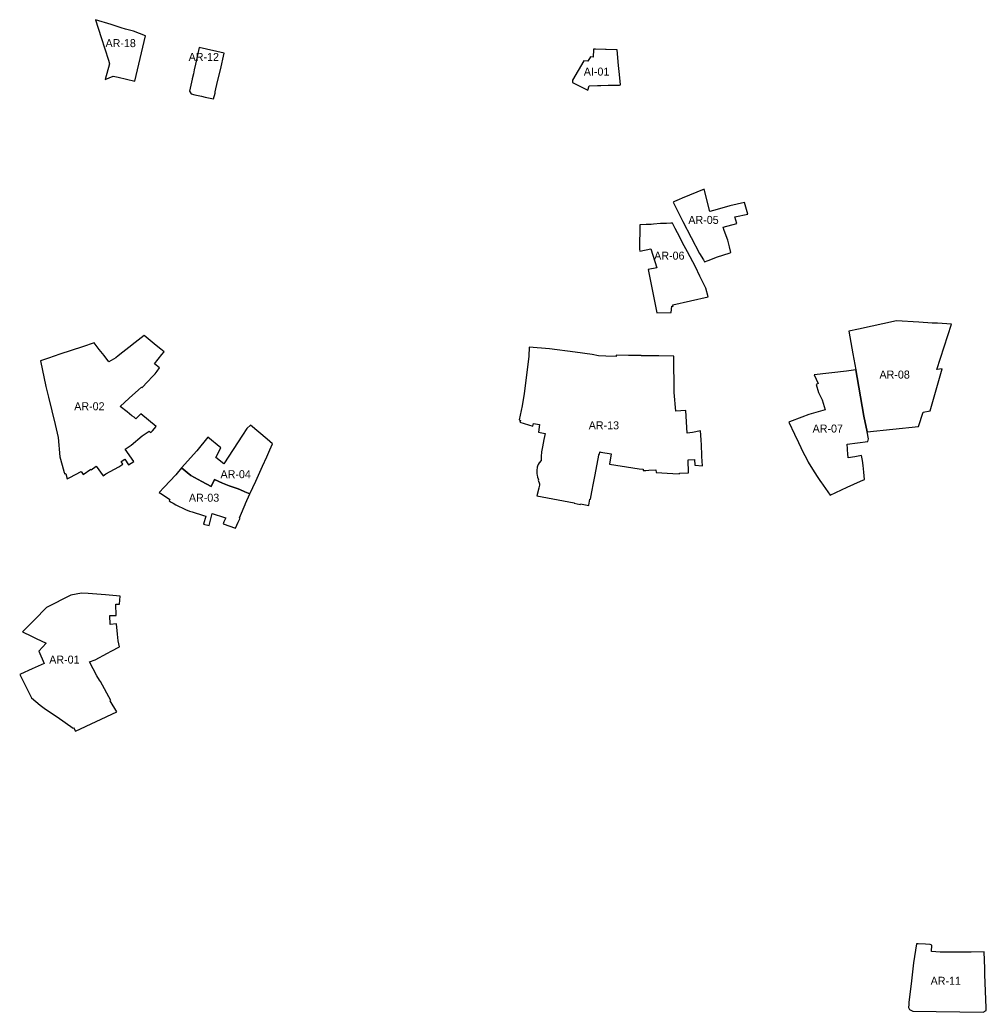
# Model space of a CAD drawing. Extents: x 428342 to 437063, y 4455780 to 4463043.
# Drawn here: x 432214 to 432818, y 4459120 to 4459741 of the extents above; entities that cross this region are included whole.
import ezdxf

# ---------------------------------------------------------------- set-up
doc = ezdxf.new("R2010")
doc.units = 0
doc.layers.add('AMB_SUNC-Residenciales', color=7, linetype='Continuous')
doc.layers.add('AMB_SUNC-Txt', color=7, linetype='Continuous')

msp = doc.modelspace()

# ---------------------------------------------------------------- linework, layer by layer
at = {"layer": 'AMB_SUNC-Residenciales'}
for points in [[(432270.35, 4459713.21), (432267.73, 4459703.42), (432272.76, 4459705.39), (432275.92, 4459704.68), (432286.32, 4459702.35), (432292.84, 4459730.56), (432285.51, 4459733.43), (432280.41, 4459734.7), (432277.62, 4459735.58), (432276.44, 4459735.97), (432271.44, 4459737.62), (432261.68, 4459740.6), (432265.15, 4459729.51), (432269.69, 4459715.37), (432270.35, 4459713.21)], [(432342.14, 4459719.79), (432326.52, 4459723.22), (432324.25, 4459712.99), (432323.44, 4459709.32), (432322.91, 4459706.96), (432322.19, 4459703.71), (432322.14, 4459703.52), (432320.34, 4459696.08), (432321.48, 4459694.34), (432323.81, 4459693.8), (432327.86, 4459692.88), (432330.27, 4459692.36), (432335.52, 4459691.23), (432336.37, 4459694.86), (432336.55, 4459695.66), (432338.01, 4459702.16), (432339.77, 4459709.35), (432342.14, 4459719.79)], [(432569.51, 4459714.84), (432566.86, 4459714.98), (432559.8, 4459702.83), (432559.91, 4459701.51), (432563.12, 4459699.68), (432564.42, 4459699.06), (432569.51, 4459696.65), (432570.25, 4459699.43), (432575.45, 4459699.48), (432577.63, 4459699.56), (432582.17, 4459699.68), (432588.31, 4459699.75), (432589.27, 4459699.85), (432589.85, 4459699.91), (432589.18, 4459706.35), (432588.59, 4459712.15), (432587.67, 4459721.79), (432580.79, 4459721.98), (432580.54, 4459721.99), (432574.23, 4459722.25), (432572.97, 4459722.3), (432572.96, 4459722.1), (432572.8, 4459717.31), (432571.17, 4459717.43), (432569.51, 4459714.84)], [(432628.44, 4459629.17), (432626.54, 4459628.31), (432623.62, 4459627), (432622.77, 4459626.65), (432628.84, 4459614.53), (432639.28, 4459594.68), (432641.69, 4459590.58), (432642.37, 4459589.38), (432644.64, 4459590.25), (432650.44, 4459592.46), (432657.72, 4459594.79), (432658.76, 4459595.13), (432657.9, 4459598.73), (432656.91, 4459602.88), (432654.67, 4459608.98), (432654, 4459611.1), (432662.45, 4459613.3), (432661.37, 4459617.5), (432669.38, 4459619.27), (432668.99, 4459620.66), (432667.31, 4459626.56), (432658.07, 4459624.28), (432650.23, 4459622.09), (432645.68, 4459620.87), (432642.03, 4459634.71), (432637.63, 4459632.92), (432628.44, 4459629.17)], [(432624.07, 4459610.27), (432622.38, 4459613.54), (432621.28, 4459613.5), (432618.64, 4459613.4), (432614.81, 4459613.25), (432610.49, 4459612.87), (432609.02, 4459612.78), (432605.86, 4459612.62), (432601.92, 4459612.42), (432601.64, 4459597.33), (432601.91, 4459596.05), (432608.83, 4459597.54), (432612.62, 4459585.66), (432607.06, 4459584.51), (432611.24, 4459563.86), (432612.51, 4459557.59), (432621.42, 4459557.64), (432621.9, 4459561.57), (432622.74, 4459561.71), (432622.51, 4459562.54), (432644.57, 4459567.52), (432643.09, 4459572.95), (432639.46, 4459580.5), (432636.69, 4459586.35), (432631.67, 4459595.62), (432629.68, 4459599.45), (432625.53, 4459607.45), (432624.07, 4459610.27)], [(432741.87, 4459492.97), (432744.01, 4459483.08), (432776.05, 4459486.51), (432778.94, 4459495.45), (432783.39, 4459496.18), (432790.86, 4459522.43), (432787.59, 4459522.13), (432796.76, 4459550.45), (432788.03, 4459550.95), (432784.54, 4459551.15), (432776.27, 4459551.64), (432762.42, 4459552.54), (432738.59, 4459547.39), (432732.57, 4459546.08), (432735.12, 4459531.88), (432736.92, 4459521.86), (432737.79, 4459517.06), (432741.87, 4459492.97)], [(432299.49, 4459537.19), (432292.18, 4459543.43), (432290.26, 4459541.92), (432286.48, 4459538.97), (432282.59, 4459535.93), (432278.76, 4459532.95), (432275.87, 4459530.69), (432274.27, 4459529.45), (432270.04, 4459526.96), (432266.99, 4459530.78), (432263.94, 4459534.62), (432260.73, 4459538.67), (432253.53, 4459536.31), (432239.37, 4459531.66), (432232.3, 4459529.25), (432227.23, 4459527.51), (432230.7, 4459511.44), (432231.5, 4459508.15), (432232.33, 4459504.73), (432236.51, 4459487.66), (432238.4, 4459479.69), (432239.35, 4459467.46), (432240.84, 4459462.31), (432242.05, 4459457.83), (432242.28, 4459456.92), (432243, 4459457.11), (432243.03, 4459456.97), (432244.03, 4459453.75), (432245.61, 4459454.59), (432252.65, 4459458.36), (432253.96, 4459456.44), (432258.73, 4459459.72), (432259, 4459459.37), (432262.02, 4459461.63), (432266.42, 4459455.72), (432268.03, 4459456.92), (432276.31, 4459461.31), (432278.81, 4459462.89), (432277.74, 4459464.57), (432279.99, 4459466), (432282.25, 4459462.43), (432285.64, 4459464.59), (432280.24, 4459472.34), (432283.96, 4459474.9), (432290.82, 4459480.74), (432295.22, 4459483.62), (432296.32, 4459482.76), (432297.22, 4459483.8), (432299.59, 4459486.52), (432290.09, 4459494.48), (432286.88, 4459491.29), (432285.93, 4459492.21), (432284.4, 4459493.24), (432281.41, 4459495.61), (432277.13, 4459499.01), (432282.71, 4459504.14), (432288.57, 4459509.46), (432290.41, 4459511.03), (432290.78, 4459510.78), (432294.16, 4459514.42), (432297.29, 4459517.69), (432298.97, 4459519.45), (432300.14, 4459521.01), (432301.66, 4459523.05), (432298.47, 4459525.72), (432303.21, 4459531.45), (432304.6, 4459533.17), (432302.44, 4459534.76), (432299.49, 4459537.19)], [(432631.42, 4459482.24), (432630.58, 4459496.38), (432624.4, 4459496.06), (432623.39, 4459507.79), (432623.24, 4459530.41), (432613.77, 4459530.6), (432608.49, 4459530.6), (432602.84, 4459530.62), (432602.82, 4459530.83), (432594.91, 4459530.91), (432587.14, 4459531), (432587.11, 4459530.3), (432580.7, 4459530.48), (432576.1, 4459530.73), (432572.17, 4459531.42), (432561.58, 4459532.95), (432545.46, 4459534.97), (432532.83, 4459535.95), (432532.44, 4459530.5), (432531.46, 4459521.96), (432529.55, 4459507.12), (432528.37, 4459499.45), (432526.47, 4459490.54), (432527.24, 4459490.16), (432526.89, 4459489.22), (432534.96, 4459486.71), (432535.36, 4459488.28), (432539.1, 4459487.69), (432538.57, 4459483.03), (432542.74, 4459482.19), (432541.88, 4459478.37), (432540.97, 4459473.69), (432540.53, 4459470.69), (432540.32, 4459467.67), (432540.16, 4459465.29), (432538.99, 4459463.73), (432538.45, 4459462.76), (432538, 4459461.66), (432537.78, 4459460.97), (432537.67, 4459460.43), (432537.56, 4459459.64), (432537.46, 4459458.65), (432537.47, 4459457.48), (432537.53, 4459456.82), (432537.69, 4459456.01), (432538.04, 4459454.76), (432538.52, 4459453.4), (432538.46, 4459453.02), (432539.21, 4459450.61), (432539.12, 4459449.81), (432538.73, 4459448.17), (432538.7, 4459448.04), (432537.56, 4459443.15), (432560.93, 4459438.69), (432560.89, 4459438.54), (432564.68, 4459437.75), (432564.76, 4459438.12), (432570.06, 4459437.2), (432570.09, 4459437.35), (432570.71, 4459441.16), (432571.03, 4459441.1), (432571.89, 4459445.64), (432572.92, 4459451.03), (432573.94, 4459456.31), (432576.32, 4459468.59), (432576.38, 4459468.88), (432576.74, 4459469.16), (432576.95, 4459470.6), (432577.61, 4459470.48), (432584.01, 4459469.35), (432582.89, 4459462.89), (432597.48, 4459460.64), (432601.51, 4459460.09), (432604.04, 4459459.75), (432603.96, 4459458.98), (432604.78, 4459458.96), (432605.57, 4459458.96), (432607.54, 4459459.09), (432612.01, 4459459.39), (432612.22, 4459457.81), (432622.59, 4459457.13), (432626.76, 4459456.86), (432626.77, 4459457.39), (432632.23, 4459457.42), (432632.07, 4459465.64), (432636.12, 4459465.86), (432636.21, 4459462.24), (432641.01, 4459461.93), (432640.7, 4459467.81), (432640.39, 4459475.63), (432640.32, 4459477.4), (432640.29, 4459478.18), (432639.87, 4459483.67), (432634.81, 4459482.8), (432631.42, 4459482.24)], [(432744.92, 4459478.85), (432744.01, 4459483.08), (432741.87, 4459492.97), (432737.79, 4459517.06), (432736.92, 4459521.86), (432731, 4459521.15), (432710.97, 4459518.75), (432713.33, 4459513.28), (432712.19, 4459512.77), (432713.68, 4459507.7), (432715.85, 4459503.12), (432717.73, 4459496.99), (432707.48, 4459493.95), (432703.08, 4459492.36), (432695.38, 4459489.32), (432695.02, 4459489.18), (432698.63, 4459481.69), (432701.18, 4459476.41), (432702.63, 4459473.37), (432704.08, 4459470.33), (432706, 4459466.57), (432707.13, 4459464.16), (432709.87, 4459459.76), (432712.81, 4459455.19), (432714.93, 4459452.09), (432715.12, 4459451.81), (432720.8, 4459443.53), (432731.54, 4459448.54), (432739.87, 4459452.3), (432742.41, 4459453.35), (432741.93, 4459457.9), (432741.49, 4459462.1), (432741.1, 4459465.22), (432740.53, 4459468.34), (432736.35, 4459467.61), (432732.16, 4459466.87), (432731.95, 4459469.65), (432731.79, 4459471.68), (432731.73, 4459472.53), (432731.52, 4459475.42), (432744.45, 4459477.13), (432744.92, 4459478.85)], [(432328.05, 4459452.13), (432334.06, 4459449.01), (432336.09, 4459453.43), (432341.1, 4459451.1), (432345.21, 4459449.43), (432350.12, 4459447.71), (432351.79, 4459447.08), (432355.04, 4459445.68), (432358.2, 4459444.32), (432361.86, 4459452.38), (432366.05, 4459461.61), (432368.7, 4459467.45), (432370.72, 4459471.9), (432372.38, 4459475.55), (432368.97, 4459478.48), (432358.64, 4459487.33), (432356.35, 4459485.19), (432353.61, 4459481.04), (432341.83, 4459463.23), (432336.92, 4459467.05), (432340.09, 4459473.15), (432331.8, 4459479.72), (432324.92, 4459471.25), (432315.52, 4459460.6), (432321.34, 4459455.83), (432328.05, 4459452.13)], [(432301.54, 4459445.33), (432303.56, 4459443.97), (432308.19, 4459440.85), (432307.74, 4459440.01), (432308.97, 4459439.29), (432310.22, 4459438.57), (432311.88, 4459437.62), (432317.88, 4459434.54), (432320.47, 4459433.66), (432322.1, 4459433.18), (432329.13, 4459430.87), (432330.53, 4459430.53), (432329.22, 4459425.44), (432332.62, 4459424.56), (432334.6, 4459432.19), (432342.4, 4459429.61), (432343.06, 4459429.32), (432341.91, 4459426.9), (432341.48, 4459425.59), (432349.13, 4459423.04), (432350.81, 4459426.6), (432352.04, 4459429.23), (432351.61, 4459429.42), (432352.23, 4459430.87), (432355.12, 4459437.68), (432355.42, 4459438.39), (432358.2, 4459444.32), (432355.04, 4459445.68), (432351.79, 4459447.08), (432350.12, 4459447.71), (432345.21, 4459449.43), (432341.1, 4459451.1), (432336.09, 4459453.43), (432334.06, 4459449.01), (432328.05, 4459452.13), (432321.34, 4459455.83), (432315.52, 4459460.6), (432311.79, 4459456.19), (432304.57, 4459448.54), (432301.54, 4459445.33)], [(432247.93, 4459298.38), (432249.23, 4459296.17), (432274.95, 4459308.1), (432270.93, 4459315.13), (432271.25, 4459315.31), (432264.85, 4459327.1), (432264.24, 4459327.99), (432262.49, 4459330.57), (432257.9, 4459339.42), (432261.47, 4459340.72), (432269.08, 4459344.87), (432271.49, 4459346.13), (432276.65, 4459348.83), (432275.73, 4459352.51), (432275.39, 4459356.69), (432274.87, 4459363.12), (432270.84, 4459362.73), (432270.52, 4459368.41), (432274.49, 4459368.31), (432274.35, 4459375.38), (432276.64, 4459375.37), (432277.13, 4459380.53), (432267.93, 4459381.18), (432257.16, 4459382.06), (432252.89, 4459382.33), (432246.27, 4459381.06), (432231.05, 4459373.41), (432223.5, 4459365.76), (432215.95, 4459358.12), (432221.69, 4459355.39), (432224.6, 4459354.01), (432230.75, 4459351.08), (432226.24, 4459346.02), (432229.64, 4459338.36), (432222.1, 4459335.01), (432214.85, 4459331.8), (432214.37, 4459331.59), (432221.67, 4459316.87), (432224.33, 4459314.59), (432226.99, 4459312.31), (432230.5, 4459309.82), (432237.64, 4459305.12), (432247.62, 4459298.06), (432247.93, 4459298.38)], [(432803.7, 4459158), (432795.37, 4459158.04), (432789.66, 4459157.93), (432784.2, 4459158.42), (432784.47, 4459162.44), (432783.36, 4459162.83), (432780.42, 4459162.92), (432775.93, 4459163.22), (432774.9, 4459163.23), (432773.07, 4459151.38), (432771.6, 4459138.21), (432770.16, 4459126.77), (432770.09, 4459126.18), (432769.98, 4459125.29), (432769.9, 4459123.46), (432770.48, 4459122.25), (432772.53, 4459121.04), (432816.6, 4459120.49), (432818.39, 4459121.62), (432818.35, 4459123.25), (432817.6, 4459143.99), (432817.53, 4459147.73), (432817.14, 4459158.26), (432808.98, 4459157.95), (432803.7, 4459158)]]:
    msp.add_lwpolyline(points, dxfattribs=at)

# ---------------------------------------------------------------- texts
at = {"layer": 'AMB_SUNC-Txt'}
for s, p in [('AR-18', (432267.92, 4459723.56)), ('AR-12', (432319.88, 4459714.92)), ('AI-01', (432566.88, 4459705.76)), ('AR-05', (432632.23, 4459613.07)), ('AR-06', (432610.88, 4459590.74)), ('AR-08', (432751.71, 4459516.43)), ('AR-02', (432248.36, 4459496.62)), ('AR-13', (432569.97, 4459484.7)), ('AR-07', (432709.9, 4459482.7)), ('AR-04', (432339.8, 4459454.18)), ('AR-03', (432320.05, 4459439.47)), ('AR-01', (432232.73, 4459338.3)), ('AR-11', (432783.67, 4459137.58))]:
    msp.add_text(s, height=5, dxfattribs=at).set_placement(p)

doc.saveas('drawing.dxf')
